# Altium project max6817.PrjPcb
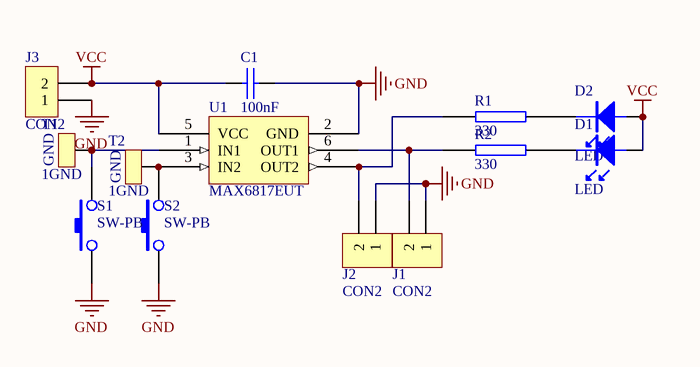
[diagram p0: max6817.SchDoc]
1 sheet, 13 parts. Net scope: global (net labels, ports and power ports of the same name join across sheets).
Board file: max6817.PcbDoc

## Sheet max6817.SchDoc
size A4

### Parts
C1  100nF  [0805]
D1  LED  [1206_LED]
D2  LED  [1206_LED]
J1  CON2  [ARK2]
J2  CON2  [ARK2]
J3  CON2  [ARK2]
R1  330  [0805]
R2  330  [0805]
S1  SW-PB  [U_SW]
S2  SW-PB  [U_SW]
T1  1GND  [1GND]
T2  1GND  [1GND]
U1  MAX6817EUT  [SOT23-6]

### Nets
GND: C1.2 J1.1 J2.1 J3.1 S1.1 S2.1 U1.2(GND)
VCC: C1.1 D1.1(A) D2.1(A) J3.2 U1.5(VCC)
NetD1_2: D1.2(K) R2.2
NetD2_2: D2.2(K) R1.2
NetJ1_2: J1.2 R2.1 U1.6(OUT1)
NetJ2_2: J2.2 R1.1 U1.4(OUT2)
NetS1_2: S1.2 T1.1(CON2) U1.1(IN1)
NetS2_2: S2.2 T2.1(CON2) U1.3(IN2)

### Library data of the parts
C1 = Cap: Capacitor
J1-J3 = CON2: Connector
R1 R2 = RES2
